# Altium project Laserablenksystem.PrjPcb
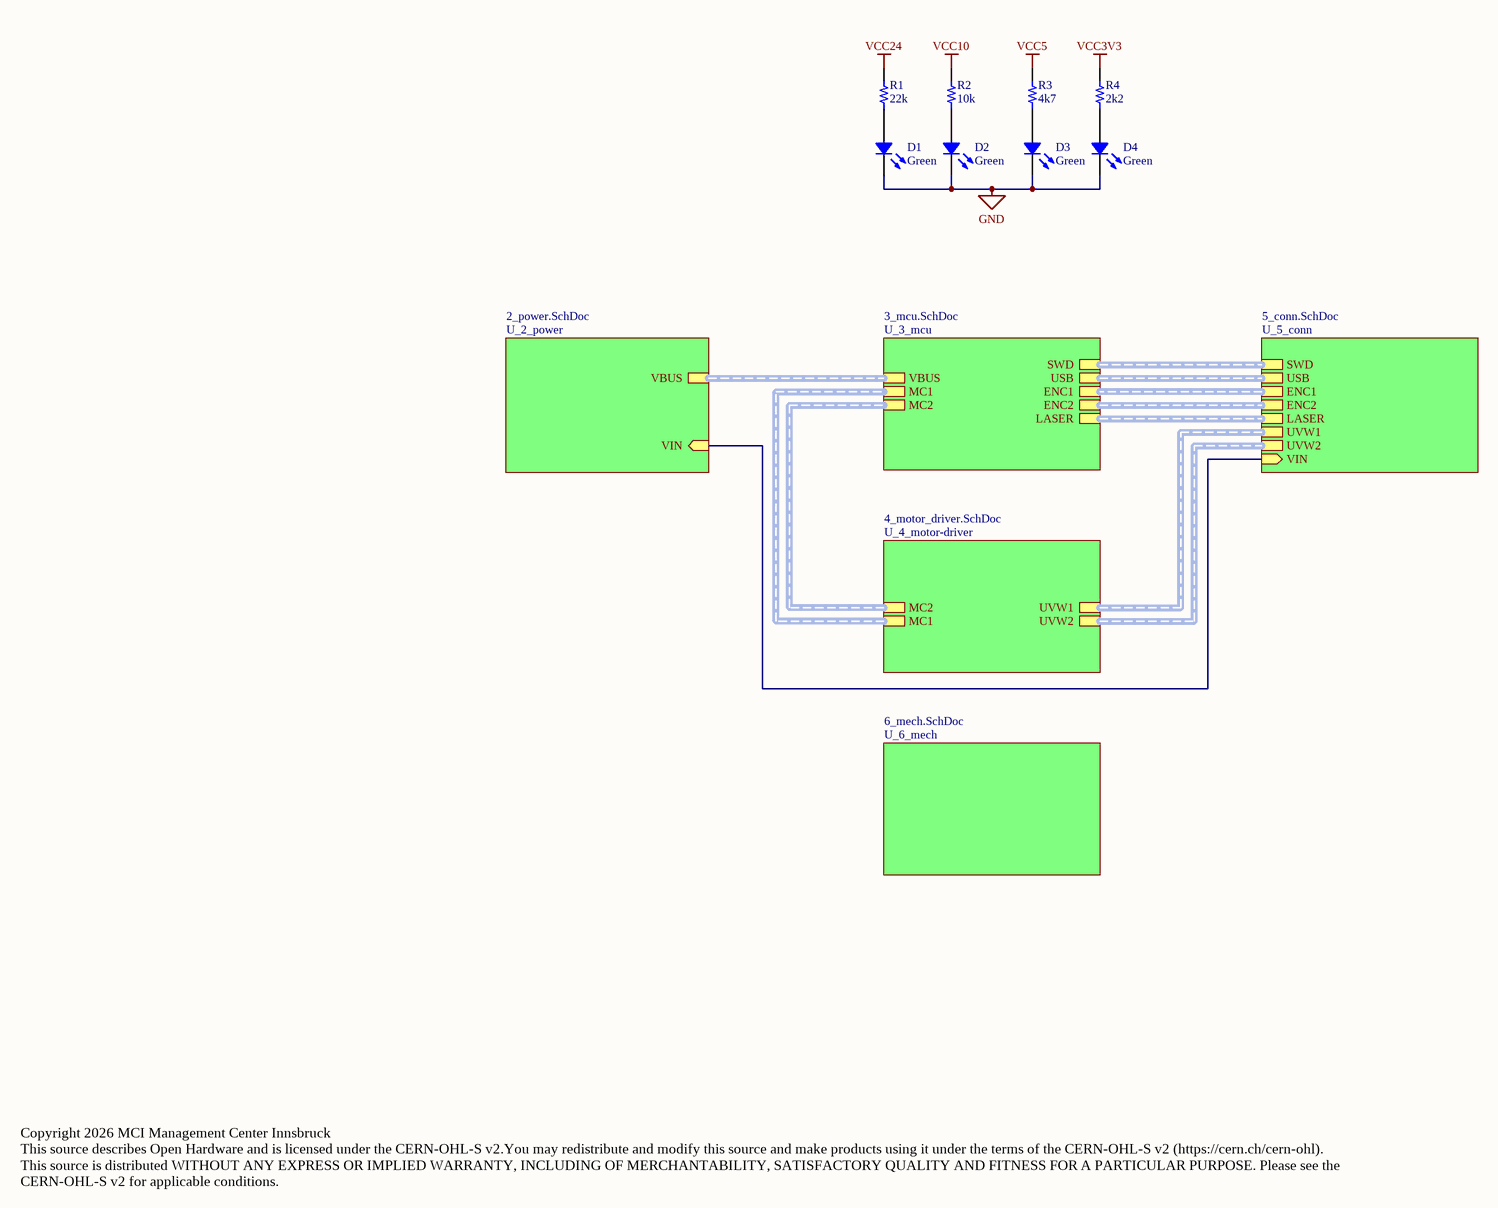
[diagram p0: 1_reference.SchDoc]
6 sheets, 152 parts. Net scope: hierarchical (ports join the sheet entries above them; power ports are global).
Board file: Laserablenksystem.PcbDoc
Sheets:
  1_reference.SchDoc
    U_2_power = 2_power.SchDoc
    U_3_mcu = 3_mcu.SchDoc
    U_5_conn = 5_conn.SchDoc
    U_4_motor-driver = 4_motor_driver.SchDoc
    U_6_mech = 6_mech.SchDoc

## Sheet 1_reference.SchDoc: Reference
size A3; CompanyName: MCI Management Center Innsbruck; Address1: Universitätsstraße 15; Address2: A-6020 Innsbruck; Revision: 1.0; SheetNumber: 1; SheetTotal: 6

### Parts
D1  Green  [LED 0805_2012 GREEN]
D2  Green  [LED 0805_2012 GREEN]
D3  Green  [LED 0805_2012 GREEN]
D4  Green  [LED 0805_2012 GREEN]
R1  22k  [RES 0603_1608]
R2  10k  [RES 0603_1608]
R3  4k7  [RES 0603_1608]
R4  2k2  [RES 0603_1608]

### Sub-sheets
U_2_power = 2_power.SchDoc: VBUS (harness Supply), VIN (in)
U_3_mcu = 3_mcu.SchDoc: MC1 (harness MC1), MC2 (harness MC2), SWD (harness SWD), USB (harness USB-C), ENC1 (harness ENC1), ENC2 (harness ENC2), LASER (harness LASER), VBUS (harness Supply)
U_4_motor-driver = 4_motor_driver.SchDoc: UVW1 (harness UVW1), UVW2 (harness UVW2), MC1 (harness MC1), MC2 (harness MC2)
U_5_conn = 5_conn.SchDoc: SWD (harness SWD), USB (harness USB-C), ENC1 (harness ENC1), ENC2 (harness ENC2), LASER (harness LASER), UVW1 (harness UVW1), UVW2 (harness UVW2), VIN (in)
U_6_mech = 6_mech.SchDoc: no entries

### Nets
GND: D1.2 D2.2 D3.2 D4.2
VCC3V3: R4.2
VCC5: R3.2
VCC10: R2.2
VCC24: R1.2
NetC2_2: sheet U_2_power/VIN, sheet U_5_conn/VIN
NetD1_1: D1.1 R1.1
NetD2_1: D2.1 R2.1
NetD3_1: D3.1 R3.1
NetD4_1: D4.1 R4.1

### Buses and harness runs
harness sheet U_2_power/VBUS = sheet U_3_mcu/VBUS
harness sheet U_3_mcu/ENC1 = sheet U_5_conn/ENC1
harness sheet U_3_mcu/ENC2 = sheet U_5_conn/ENC2
harness sheet U_3_mcu/LASER = sheet U_5_conn/LASER
harness sheet U_3_mcu/MC1 = sheet U_4_motor-driver/MC1
harness sheet U_3_mcu/MC2 = sheet U_4_motor-driver/MC2
harness sheet U_3_mcu/SWD = sheet U_5_conn/SWD
harness sheet U_3_mcu/USB = sheet U_5_conn/USB
harness sheet U_4_motor-driver/UVW1 = sheet U_5_conn/UVW1
harness sheet U_4_motor-driver/UVW2 = sheet U_5_conn/UVW2

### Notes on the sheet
- Copyright 2026 MCI Management Center Innsbruck
  This source describes Open Hardware and is licensed under the CERN-OHL-S v2.You may redistribute and modify this source and make products using it under the terms of the CERN-OHL-S v2 (https://cern.ch/cern-ohl).
  This source is distributed WITHOUT ANY EXPRESS OR IMPLIED WARRANTY, INCLUDING OF MERCHANTABILITY, SATISFACTORY QUALITY AND FITNESS FOR A PARTICULAR PURPOSE. Please see the CERN-OHL-S v2 for applicable conditions.

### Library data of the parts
D1-D4 = 5988170107F: LED GREEN CLEAR 0805 SMD; Manufacturer: Dialight; Configuration: Standard; Current - Test: 20mA; Lens Color: Colorless; Lens Size: 1.40mm x 1.25mm; Lens Style: Rectangle with Flat Top; Millicandela Rating: 20mcd; Viewing Angle: 140°; Voltage - Forward (Vf) (Typ): 2V; Wavelength - Dominant: 566nm
R1 = RC0603JR-1322KL: RES 22K OHM 5% 1/10W 0603; Manufacturer: Yageo; Power (Watts): 0.1W, 1/10W; Resistance: 22 kOhms; Temperature Coefficient: ±100ppm/°C
R2 = CRCW060310K0FKEA: RES SMD 10K OHM 1% 1/10W 0603; Manufacturer: Vishay Dale; Power (Watts): 0.1W, 1/10W; Resistance: 10 kOhms; Temperature Coefficient: ±100ppm/°C
R3 = RC0603JR-134K7L: RES 4.7K OHM 5% 1/10W 0603; Manufacturer: Yageo; Power (Watts): 0.1W, 1/10W; Resistance: 4.7 kOhms; Temperature Coefficient: ±100ppm/°C
R4 = RC0603JR-132K2L: RES 2.2K OHM 5% 1/10W 0603; Manufacturer: Yageo; Power (Watts): 0.1W, 1/10W; Resistance: 2.2 kOhms; Temperature Coefficient: ±100ppm/°C

## Sheet 2_power.SchDoc: Power Supply
size A3; CompanyName: MCI Management Center Innsbruck; Address1: Universitätsstraße 15; Address2: A-6020 Innsbruck; SheetNumber: 2; SheetTotal: 6
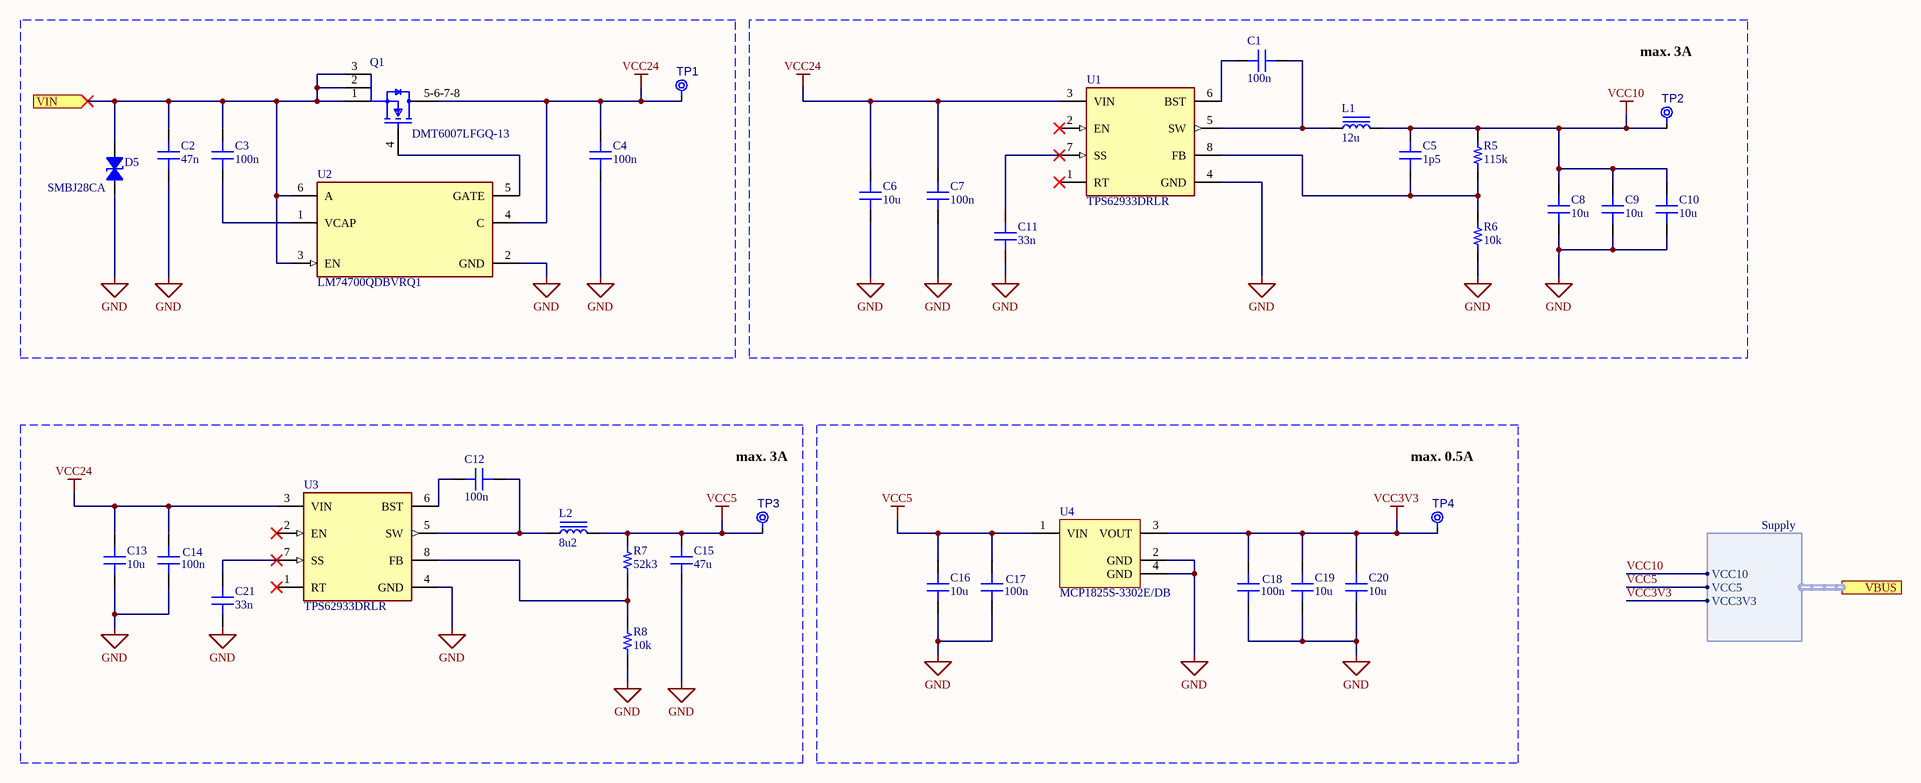
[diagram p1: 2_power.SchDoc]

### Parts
C1  Capacitance: 100n  [CAP 0805_2012]  (hidden comment: 0.1 µF)
C2  Capacitance: 47n  [CAP 0805_2012]  (hidden comment: 0.047µF)
C3  Capacitance: 100n  [CAP 0805_2012]  (hidden comment: 0.1 µF)
C4  Capacitance: 100n  [CAP 0805_2012]  (hidden comment: 0.1 µF)
C5  Capacitance: 1p5  [CAP 0603_1608]  (hidden comment: 1.5 pF)
C6  Capacitance: 10u  [CAP 1206_3216 - 0.8MM]  (hidden comment: 10 µF)
C7  Capacitance: 100n  [CAP 0805_2012]  (hidden comment: 0.1 µF)
C8  Capacitance: 10u  [CAP 1206_3216 - 0.8MM]  (hidden comment: 10 µF)
C9  Capacitance: 10u  [CAP 1206_3216 - 0.8MM]  (hidden comment: 10 µF)
C10  Capacitance: 10u  [CAP 1206_3216 - 0.8MM]  (hidden comment: 10 µF)
C11  Capacitance: 33n  [CAP 0603_1608]  (hidden comment: 0.033 µF)
C12  Capacitance: 100n  [CAP 0805_2012]  (hidden comment: 0.1 µF)
C13  Capacitance: 10u  [CAP 1206_3216 - 0.8MM]  (hidden comment: 10 µF)
C14  Capacitance: 100n  [CAP 0805_2012]  (hidden comment: 0.1 µF)
C15  47u  [CAP 1210_3225 - 1MM]
C16  Capacitance: 10u  [CAP 1206_3216 - 0.8MM]  (hidden comment: 10 µF)
C17  Capacitance: 100n  [CAP 0805_2012]  (hidden comment: 0.1 µF)
C18  Capacitance: 100n  [CAP 0805_2012]  (hidden comment: 0.1 µF)
C19  Capacitance: 10u  [CAP 1206_3216 - 0.8MM]  (hidden comment: 10 µF)
C20  Capacitance: 10u  [CAP 1206_3216 - 0.8MM]  (hidden comment: 10 µF)
C21  Capacitance: 33n  [CAP 0603_1608]  (hidden comment: 0.033 µF)
D5  SMBJ28CA  [DO214AA SMB]
L1  value 12u  [SDR1307120ML]  (hidden comment: SDR1307-120ML)
L2  value 8u2  [FP-IHLP-5050EZ-FP_3_226x4-MFG]  (hidden comment: IHLP5050EZER8R2M01)
Q1  DMT6007LFGQ-13  [FP-POWERDI3333-8-MFG]
R5  115k  [RES 0603_1608]
R6  10k  [RES 0603_1608]
R7  52k3  [RES 0603_1608]
R8  10k  [RES 0603_1608]
TP1  TPAD6R  [TP06R]  (value not drawn)  (no BOM)
TP2  TPAD6R  [TP06R]  (value not drawn)  (no BOM)
TP3  TPAD6R  [TP06R]  (value not drawn)  (no BOM)
TP4  TPAD6R  [TP06R]  (value not drawn)  (no BOM)
U1  TPS62933DRLR  [FP-DRL0008A-MFG]
U2  LM74700QDBVRQ1  [FP-DBV0006A-MFG]
U3  TPS62933DRLR  [FP-DRL0008A-MFG]
U4  MCP1825S-3302E/DB  [SOT-223-DB3_N]

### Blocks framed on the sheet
max. 3A: C1 C5-C11 L1 R5 R6 TP2 U1
max. 3A: C12-C15 C21 L2 R7 R8 TP3 U3
max. 0.5A: C16-C20 TP4 U4

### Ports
VBUS (harness Supply, see 1_reference[3B], 3_mcu[1A]), VIN (in, see 1_reference[3B], 5_conn[6A])

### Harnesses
Supply: VCC5, VCC10, VCC3V3

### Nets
GND: C2.1 C4.1 C6.1 C7.1 C8.1 C9.1 C10.1 C11.1 C13.1 C14.1 C15.1 C16.1 C17.1 C18.1 C19.1 C20.1 C21.1 D5.2 R6.1 R8.1 U1.4(GND) U2.2(GND) U3.4(GND) U4.2(GND) U4.4(GND)
VCC3V3: C18.2 C19.2 C20.2 TP4.1(TP) U4.3(VOUT) ; port VBUS.VCC3V3
VCC5: C15.2 C16.2 C17.2 L2.2 R7.2 TP3.1(TP) U4.1(VIN) ; port VBUS.VCC5
VCC10: C5.2 C8.2 C9.2 C10.2 L1.2 R5.2 TP2.1(TP) ; port VBUS.VCC10
VCC24: C4.2 C6.2 C7.2 C13.2 C14.2 Q1.5-6-7-8(D) TP1.1(TP) U1.3(VIN) U2.4(C) U3.3(VIN)
NetC1_1: C1.1 L1.1 U1.5(SW)
NetC1_2: C1.2 U1.6(BST)
NetC2_2: C2.2 C3.2 D5.1 Q1.1(S) Q1.2(S) Q1.3(S) U2.3(EN) U2.6(A) ; port VIN
NetC3_1: C3.1 U2.1(VCAP)
NetC5_1: C5.1 R5.1 R6.2 U1.8(FB)
NetC11_2: C11.2 U1.7(SS)
NetC12_1: C12.1 L2.1 U3.5(SW)
NetC12_2: C12.2 U3.6(BST)
NetC21_2: C21.2 U3.7(SS)
NetQ1_4: Q1.4(G) U2.5(GATE)
NetR7_1: R7.1 R8.2 U3.8(FB)

Not connected (* = marked no-connect by the designer): U1 1(RT)* 2(EN)*; U3 1(RT)* 2(EN)*

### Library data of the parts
C1 C3 C4 C7 C12 C14 C17 C18 = CC0805JRX7R9BB104: CAP CER 0.1UF 50V X7R 0805; manufacturer: Yageo; Tolerance: ±5%
C2 = 08055C473KAT2A: CAP CER 0.047UF 50V X7R 0805; manufacturer: AVX Corporation; Tolerance: ±10%
C5 = C0603C159C5GACTU: CAP CER 1.5PF 50V C0G/NP0 0603; manufacturer: KEMET; Temperature Coefficient: C0G, NP0; Tolerance: ±0.25pF
C6 C8-C10 C13 C16 C19 C20 = CL31A106KBHNNNE: CAP CER 10UF 50V X5R 1206; manufacturer: Samsung Electro-Mechanics; Tolerance: ±10%
C11 C21 = CC0603KRX7R9BB333: CAP CER 0.033UF 50V X7R 0603; manufacturer: Yageo; Tolerance: ±10%
C15 = GRM32ER71A476KE15L: CAP CER 47UF 10V X7R 1210; manufacturer: Murata Electronics; Capacitance: 47 µF; Tolerance: ±10%
D5 = SMBJ28CA: TVS DIODE 28VWM 45.4VC DO214AA; Manufacturer: Littelfuse Inc.; Bidirectional Channels: 1; Current - Peak Pulse (10/1000µs): 13.3A; Power Line Protection: No; Power - Peak Pulse: 600W; Type: Zener; Voltage - Breakdown (Min): 31.1V; Voltage - Clamping (Max) @ Ipp: 45.4V; Voltage - Reverse Standoff (Typ): 28V
L1 = CMP-006-00025-2: Inductor Power Unshielded Wirewound 12uH 20% 100KHz 25Q-Factor Ferrite 4.8A 0.03Ohm DCR T/R; Manufacturer_Name: Bourns; Q Factor: 25; Number of Circuits: 1; Saturation Current: 8A; Self Resonant Frequency: 20MHz; DC Resistance (DCR): 30mΩ
L2 = CMP-006-00024-1: Inductor Power Shielded Wirewound 8.2uH 20% 100KHz Powdered Iron 9.5A 0.0225Ohm DCR 5050 T/R; DC Resistance (DCR): 22.5mΩ; Core Material: Composite; Number of Circuits: 1; Saturation Current: 18A
Q1 = CMP-12801-000088-1: MOSFET BVDSS: 41V-60V POWERDI333; Drain to Source Voltage (Vdss): 60V; Continuous Drain Current (ID): 80A; Input Capacitance: 2.09nF; Rds On Max: 6mR; Max Power Dissipation: 62.5W
R5 = CRCW0603115KFKEA: RES SMD 115K OHM 1% 1/10W 0603; Manufacturer: Vishay Dale; Power (Watts): 0.1W, 1/10W; Resistance: 115 kOhms; Temperature Coefficient: ±100ppm/°C
R6 R8 = CRCW060310K0FKEA: as R2 on sheet 1_reference
R7 = RC0603FR-0752K3L: RES 52.3K OHM 1% 1/10W 0603; Manufacturer: Yageo; Power (Watts): 0.1W, 1/10W; Resistance: 52.3 kOhms; Temperature Coefficient: ±100ppm/°C
TP1-TP4 = CMP-00028-00002-3: 0.6mm round
U1 U3 = CMP-04918-000610-1: 3.8-V to 30-V, 3-A, 200-kHz to 2.2-MHz, low-IQ synchronous buck converter in SOT-583 package 8-SOT-5X3 -40 to 150
U2 = CMP-04910-000003-1: POWER MANAGEMENT; Manufacturer: Texas Instruments; Number Of Outputs: 1; Standoff Height: 0mm; Automotive Grade: Grade 1; Nominal Supply Current: 80uA; Max Junction Temp: +150°C; Max Supply Voltage: 65V; Min Supply Voltage: 3.2V
U4 = CMP-0136-00458-1: 500 mA, Low Voltage, Low Quiescent Current LDO Regulator, 3-Pin SOT-223, Extended Temperature

## Sheet 3_mcu.SchDoc: MCU
size A3; CompanyName: MCI Management Center Innsbruck; Address1: Universitätsstraße 15; Address2: A-6020 Innsbruck; SheetNumber: 3; SheetTotal: 6
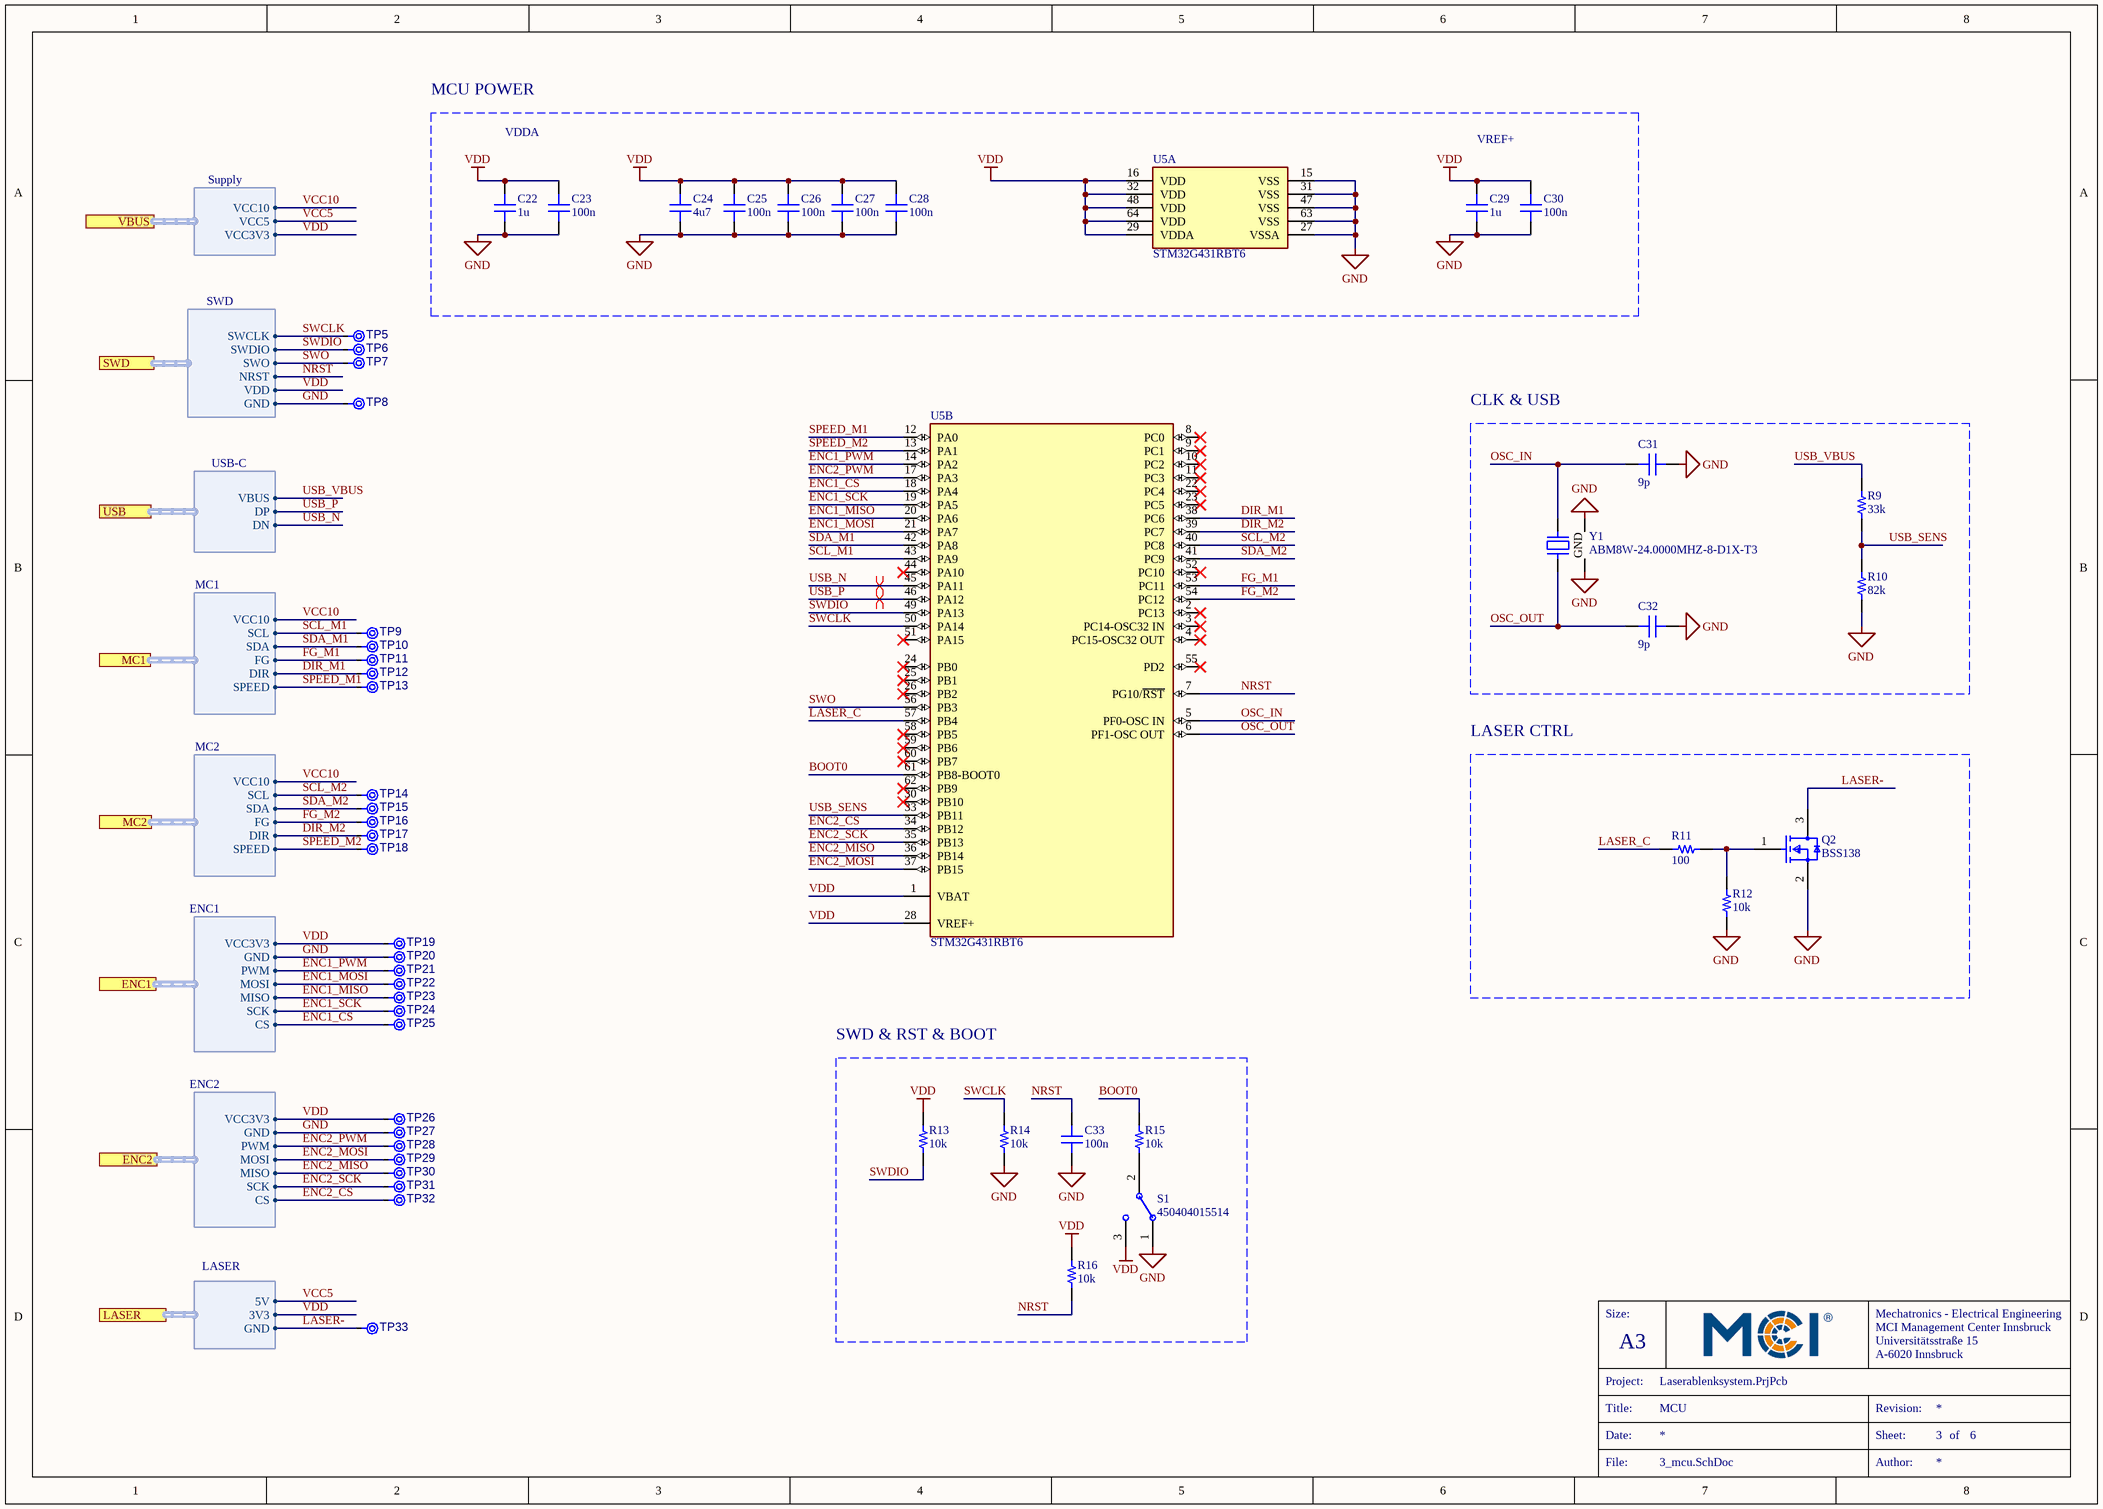
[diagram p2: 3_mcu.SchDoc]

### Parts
C22  Capacitance: 1u  [CAP 0603_1608]  (hidden comment: 1 µF)
C23  Capacitance: 100n  [CAP 0805_2012]  (hidden comment: 0.1 µF)
C24  Capacitance: 4u7  [CAP 1206_3216 - 0.8MM]  (hidden comment: 4.7 µF)
C25  Capacitance: 100n  [CAP 0805_2012]  (hidden comment: 0.1 µF)
C26  Capacitance: 100n  [CAP 0805_2012]  (hidden comment: 0.1 µF)
C27  Capacitance: 100n  [CAP 0805_2012]  (hidden comment: 0.1 µF)
C28  Capacitance: 100n  [CAP 0805_2012]  (hidden comment: 0.1 µF)
C29  Capacitance: 1u  [CAP 0603_1608]  (hidden comment: 1 µF)
C30  Capacitance: 100n  [CAP 0805_2012]  (hidden comment: 0.1 µF)
C31  Capacitance: 9p  [CAP 0402_1005]  (hidden comment: 9 pF)
C32  Capacitance: 9p  [CAP 0402_1005]  (hidden comment: 9 pF)
C33  Capacitance: 100n  [CAP 0805_2012]  (hidden comment: 0.1 µF)
Q2  BSS138  [FP-318-08-IPC_B]
R9  33k  [RES 0603_1608]
R10  82k  [RES 0603_1608]
R11  100  [RES 0603_1608]
R12  10k  [RES 0603_1608]
R13  10k  [RES 0603_1608]
R14  10k  [RES 0603_1608]
R15  10k  [RES 0603_1608]
R16  10k  [RES 0603_1608]
S1  450404015514  [WURTH WS-SLSU 450404015514]
TP5  TPAD6R  [TP06R]  (value not drawn)  (no BOM)
TP6  TPAD6R  [TP06R]  (value not drawn)  (no BOM)
TP7  TPAD6R  [TP06R]  (value not drawn)  (no BOM)
TP8  TPAD6R  [TP06R]  (value not drawn)  (no BOM)
TP9  TPAD6R  [TP06R]  (value not drawn)  (no BOM)
TP10  TPAD6R  [TP06R]  (value not drawn)  (no BOM)
TP11  TPAD6R  [TP06R]  (value not drawn)  (no BOM)
TP12  TPAD6R  [TP06R]  (value not drawn)  (no BOM)
TP13  TPAD6R  [TP06R]  (value not drawn)  (no BOM)
TP14  TPAD6R  [TP06R]  (value not drawn)  (no BOM)
TP15  TPAD6R  [TP06R]  (value not drawn)  (no BOM)
TP16  TPAD6R  [TP06R]  (value not drawn)  (no BOM)
TP17  TPAD6R  [TP06R]  (value not drawn)  (no BOM)
TP18  TPAD6R  [TP06R]  (value not drawn)  (no BOM)
TP19  TPAD6R  [TP06R]  (value not drawn)  (no BOM)
TP20  TPAD6R  [TP06R]  (value not drawn)  (no BOM)
TP21  TPAD6R  [TP06R]  (value not drawn)  (no BOM)
TP22  TPAD6R  [TP06R]  (value not drawn)  (no BOM)
TP23  TPAD6R  [TP06R]  (value not drawn)  (no BOM)
TP24  TPAD6R  [TP06R]  (value not drawn)  (no BOM)
TP25  TPAD6R  [TP06R]  (value not drawn)  (no BOM)
TP26  TPAD6R  [TP06R]  (value not drawn)  (no BOM)
TP27  TPAD6R  [TP06R]  (value not drawn)  (no BOM)
TP28  TPAD6R  [TP06R]  (value not drawn)  (no BOM)
TP29  TPAD6R  [TP06R]  (value not drawn)  (no BOM)
TP30  TPAD6R  [TP06R]  (value not drawn)  (no BOM)
TP31  TPAD6R  [TP06R]  (value not drawn)  (no BOM)
TP32  TPAD6R  [TP06R]  (value not drawn)  (no BOM)
TP33  TPAD6R  [TP06R]  (value not drawn)  (no BOM)
U5  STM32G431RBT6  [FP-LQFP64-5W-MFG]  (parts A,B of 2)
Y1  ABM8W-24.0000MHZ-8-D1X-T3  [FP-ABM8W-MFG]

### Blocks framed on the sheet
MCU POWER: C22-C30 U5
CLK & USB: C31 C32 R9 R10 Y1
LASER CTRL: Q2 R11 R12
SWD & RST & BOOT: C33 R13-R16 S1

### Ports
ENC1 (harness ENC1, see 1_reference[5B], 5_conn[1C]), ENC2 (harness ENC2, see 1_reference[5B], 5_conn[1C]), LASER (harness LASER, see 1_reference[5B], 5_conn[1D]), MC1 (harness MC1, see 1_reference[4B], 4_motor_driver[1B]), MC2 (harness MC2, see 1_reference[4B], 4_motor_driver[1B]), SWD (harness SWD, see 1_reference[5B], 5_conn[1A]), USB (harness USB-C, see 1_reference[5B], 5_conn[1B]), VBUS (harness Supply, see 1_reference[4B], 2_power[8C])

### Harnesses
SWD: SWCLK, SWDIO, GND, VDD, NRST, SWO
USB-C: DN, DP, VBUS
MC1: SPEED, DIR, FG, SDA, SCL, VCC10
MC2: SPEED, DIR, FG, SDA, SCL, VCC10
ENC1: PWM, GND, SCK, CS, VCC3V3, MOSI, MISO
ENC2: PWM, GND, SCK, CS, VCC3V3, MOSI, MISO
LASER: GND, 3V3, 5V
Supply: VCC10, VCC5, VCC3V3

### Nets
GND: C22.1 C23.1 C24.1 C25.1 C26.1 C27.1 C28.1 C29.1 C30.1 C31.1 C32.1 C33.1 Q2.2(S) R10.1 R12.1 R14.1 S1.1 TP8.1(TP) TP20.1(TP) TP27.1(TP) U5.15(VSS) U5.27(VSSA) U5.31(VSS) U5.47(VSS) U5.63(VSS) Y1.2(GND) Y1.4(GND) ; port SWD.GND, port ENC1.GND, port ENC2.GND
VCC5: port LASER.5V, port VBUS.VCC5
VCC10: port MC1.VCC10, port MC2.VCC10, port VBUS.VCC10
VDD: C22.2 C23.2 C24.2 C25.2 C26.2 C27.2 C28.2 C29.2 C30.2 R13.2 R16.2 S1.3 TP19.1(TP) TP26.1(TP) U5.1(VBAT) U5.16(VDD) U5.28(VREF+) U5.29(VDDA) U5.32(VDD) U5.48(VDD) U5.64(VDD) ; port SWD.VDD, port ENC1.VCC3V3, port ENC2.VCC3V3, port LASER.3V3, port VBUS.VCC3V3  [project net VCC3V3]
BOOT0: R15.2 U5.61(PB8-BOOT0)
DIR_M1: TP12.1(TP) U5.38(PC6) ; port MC1.DIR
DIR_M2: TP17.1(TP) U5.39(PC7) ; port MC2.DIR
ENC1_CS: TP25.1(TP) U5.18(PA4) ; port ENC1.CS
ENC1_MISO: TP23.1(TP) U5.20(PA6) ; port ENC1.MISO
ENC1_MOSI: TP22.1(TP) U5.21(PA7) ; port ENC1.MOSI
ENC1_PWM: TP21.1(TP) U5.14(PA2) ; port ENC1.PWM
ENC1_SCK: TP24.1(TP) U5.19(PA5) ; port ENC1.SCK
ENC2_CS: TP32.1(TP) U5.34(PB12) ; port ENC2.CS
ENC2_MISO: TP30.1(TP) U5.36(PB14) ; port ENC2.MISO
ENC2_MOSI: TP29.1(TP) U5.37(PB15) ; port ENC2.MOSI
ENC2_PWM: TP28.1(TP) U5.17(PA3) ; port ENC2.PWM
ENC2_SCK: TP31.1(TP) U5.35(PB13) ; port ENC2.SCK
FG_M1: TP11.1(TP) U5.53(PC11) ; port MC1.FG
FG_M2: TP16.1(TP) U5.54(PC12) ; port MC2.FG
LASER-: Q2.3(D) TP33.1(TP) ; port LASER.GND
LASER_C: R11.1 U5.57(PB4)
NRST: C33.2 R16.1 U5.7(PG10/~{RST}) ; port SWD.NRST
OSC_IN: C31.2 U5.5(PF0-OSC_IN) Y1.3
OSC_OUT: C32.2 U5.6(PF1-OSC_OUT) Y1.1
SCL_M1: TP9.1(TP) U5.43(PA9) ; port MC1.SCL
SCL_M2: TP14.1(TP) U5.40(PC8) ; port MC2.SCL
SDA_M1: TP10.1(TP) U5.42(PA8) ; port MC1.SDA
SDA_M2: TP15.1(TP) U5.41(PC9) ; port MC2.SDA
SPEED_M1: TP13.1(TP) U5.12(PA0) ; port MC1.SPEED
SPEED_M2: TP18.1(TP) U5.13(PA1) ; port MC2.SPEED
SWCLK: R14.2 TP5.1(TP) U5.50(PA14) ; port SWD.SWCLK
SWDIO: R13.1 TP6.1(TP) U5.49(PA13) ; port SWD.SWDIO
SWO: TP7.1(TP) U5.56(PB3) ; port SWD.SWO
USB_N: U5.45(PA11) ; port USB.DN
USB_P: U5.46(PA12) ; port USB.DP
USB_SENS: R9.1 R10.2 U5.33(PB11)
USB_VBUS: R9.2 ; port USB.VBUS
NetQ2_1: Q2.1(G) R11.2 R12.2
NetR15_1: R15.1 S1.2(COM)

Not connected (* = marked no-connect by the designer): U5 2(PC13)* 3(PC14-OSC32_IN)* 4(PC15-OSC32_OUT)* 8(PC0)* 9(PC1)* 10(PC2)* 11(PC3)* 22(PC4)* 23(PC5)* 24(PB0)* 25(PB1)* 26(PB2)* 30(PB10)* 44(PA10)* 51(PA15)* 52(PC10)* 55(PD2)* 58(PB5)* 59(PB6)* 60(PB7)* 62(PB9)*

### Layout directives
differential pair: USB_N, USB_P

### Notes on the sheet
- VDDA
- VREF+

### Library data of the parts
C22 C29 = EMK107B7105KA-T: CAP CER 1UF 16V X7R 0603; manufacturer: Taiyo Yuden; Tolerance: ±10%
C23 C25-C28 C30 C33 = CC0805JRX7R9BB104: as C1 on sheet 2_power
C24 = GRM31CR71H475KA12L: CAP CER 4.7UF 50V X7R 1206; manufacturer: Murata Electronics; Tolerance: ±10%
C31 C32 = CC0402CRNPO9BN9R0: CAP CER 9PF 50V C0G/NPO 0402; manufacturer: Yageo; Temperature Coefficient: C0G, NP0; Tolerance: ±0.25pF
Q2 = CMP-07173-000101-1: MOSFET N-CH 50V 220MA SOT-23; Turn-Off Delay Time: 20ns; Element Configuration: Single; Rds On Max: 3.5R; Gate to Source Voltage (Vgs): 20V; Threshold Voltage: 1.3V; Number of Elements: 1; Power Dissipation: 360mW; Rise Time: 9ns; Turn-On Delay Time: 2.5ns; Input Capacitance: 27pF; On-State Resistance: 6R
R9 = CRGCQ0603J33K: RES 33K OHM 5% 1/10W 0603; Manufacturer: TE Connectivity Passive Product; Power (Watts): 0.1W, 1/10W; Resistance: 33 kOhms; Temperature Coefficient: ±100ppm/°C
R10 = RC0603FR-1082KL: RES 82K OHM 1% 1/10W 0603; Manufacturer: Yageo; Power (Watts): 0.1W, 1/10W; Resistance: 82 kOhms; Temperature Coefficient: ±100ppm/°C
R11 = RC0603FR-07100RL: RES 100 OHM 1% 1/10W 0603; Manufacturer: Yageo; Power (Watts): 0.1W, 1/10W; Resistance: 100 Ohms; Temperature Coefficient: ±100ppm/°C
R12-R16 = CRCW060310K0FKEA: as R2 on sheet 1_reference
S1 = 450404015514: MINI SLIDE SWITCH 6.7 X 2.7 MM.; Manufacturer: Würth Elektronik; Rated Current: 300mA; Rated Voltage: 5VDC; Switching Function: On-On; Circuit: SPDT; Actuator Length: 1.50mm; Actuator Type: Standard; Contact Timing: Non-Shorting (BBM); Current Rating (Amps): 300mA (DC); Voltage Rating - DC: 5 V
TP5-TP33 = CMP-00028-00002-3: 0.6mm round
U5 = CMP-12105-000150-1: IC MCU 32BIT 128KB FLASH 64LQFP
Y1 = CMP-003-00030-1: Crystal 24MHz ±10ppm (Tol) ±20ppm (Stability) 8pF FUND 50Ohm 4-Pin SMD T/R; ESR: 25; ESR (Equivalent Series Resistance): 50Ω; Tolerance: 0.001%

## Sheet 5_conn.SchDoc: CONN
size A3; CompanyName: MCI Management Center Innsbruck; Address1: Universitätsstraße 15; Address2: A-6020 Innsbruck; SheetNumber: 5; SheetTotal: 6
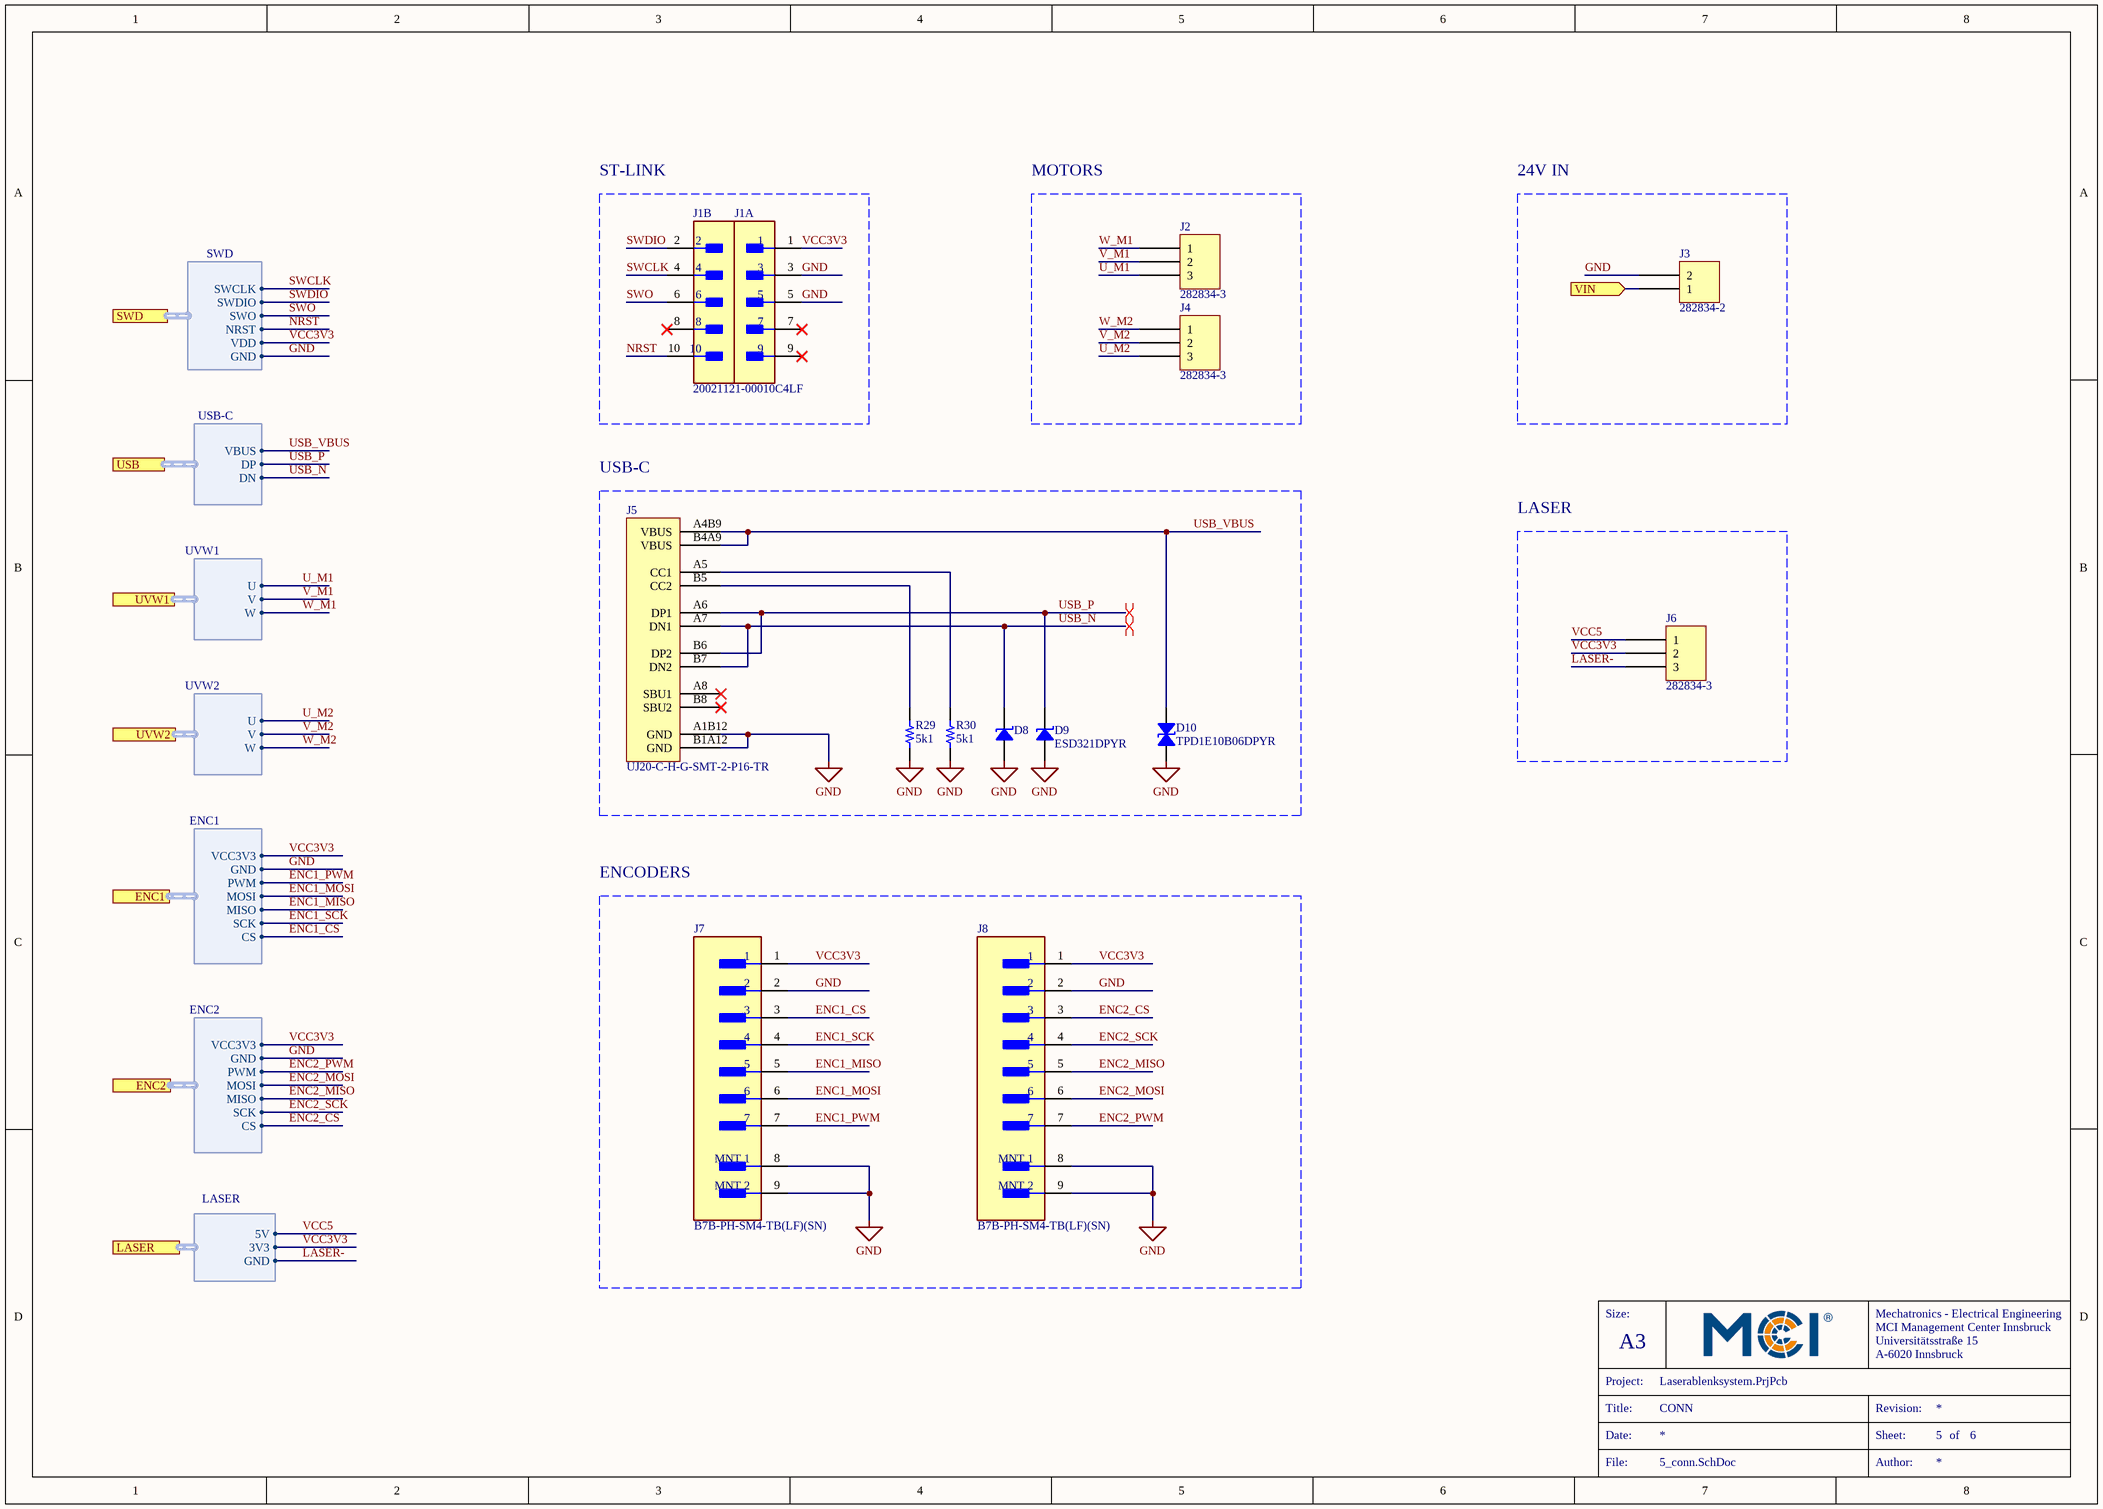
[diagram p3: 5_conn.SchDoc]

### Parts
D8  ESD321DPYR  [0402]  (value not drawn)
D9  ESD321DPYR  [0402]
D10  TPD1E10B06DPYR  [0402]
J1  20021121-00010C4LF  [FP-20021121-00010C4LF-MFG]  (value not drawn)  (parts A,B of 2)
J2  282834-3  [TE 282834-3]
J3  282834-2  [TE 282834-2]
J4  282834-3  [TE 282834-3]
J5  UJ20-C-H-G-SMT-2-P16-TR  [Same Sky UJ20-C-H-G-SMT-2-P16-TR]
J6  282834-3  [TE 282834-3]
J7  B7B-PH-SM4-TB(LF)(SN)  [FP-B7B-PH-SM4-TB_LF_SN-MFG]
J8  B7B-PH-SM4-TB(LF)(SN)  [FP-B7B-PH-SM4-TB_LF_SN-MFG]
R29  5k1  [RES 0603_1608]
R30  5k1  [RES 0603_1608]

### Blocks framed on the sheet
ST-LINK: J1
MOTORS: J2 J4
24V IN: J3
USB-C: D8-D10 J5 R29 R30
LASER: J6
ENCODERS: J7 J8

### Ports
ENC1 (harness ENC1, see 1_reference[6B], 3_mcu[1C]), ENC2 (harness ENC2, see 1_reference[6B], 3_mcu[1D]), LASER (harness LASER, see 1_reference[6B], 3_mcu[1D]), SWD (harness SWD, see 1_reference[6B], 3_mcu[1A]), USB (harness USB-C, see 1_reference[6B], 3_mcu[1B]), UVW1 (harness UVW1, see 1_reference[6B], 4_motor_driver[1C]), UVW2 (harness UVW2, see 1_reference[6B], 4_motor_driver[1C]), VIN (in, see 1_reference[6B], 2_power[1B])

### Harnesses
SWD: SWCLK, SWDIO, GND, VDD, NRST, SWO
USB-C: DN, DP, VBUS
UVW1: V, U, W
UVW2: V, U, W
ENC1: PWM, GND, SCK, CS, VCC3V3, MOSI, MISO
ENC2: PWM, GND, SCK, CS, VCC3V3, MOSI, MISO
LASER: GND, 3V3, 5V

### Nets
GND: D8.1 D9.1 D10.1 J1.3 J1.5 J3.2 J5.A1B12(GND) J5.B1A12(GND) J7.2 J7.8(MNT_1) J7.9(MNT_2) J8.2 J8.8(MNT_1) J8.9(MNT_2) R29.1 R30.1 ; port SWD.GND, port ENC1.GND, port ENC2.GND
VCC3V3: J1.1 J6.2 J7.1 J8.1 ; port SWD.VDD, port ENC1.VCC3V3, port ENC2.VCC3V3, port LASER.3V3
VCC5: J6.1 ; port LASER.5V
ENC1_CS: J7.3 ; port ENC1.CS
ENC1_MISO: J7.5 ; port ENC1.MISO
ENC1_MOSI: J7.6 ; port ENC1.MOSI
ENC1_PWM: J7.7 ; port ENC1.PWM
ENC1_SCK: J7.4 ; port ENC1.SCK
ENC2_CS: J8.3 ; port ENC2.CS
ENC2_MISO: J8.5 ; port ENC2.MISO
ENC2_MOSI: J8.6 ; port ENC2.MOSI
ENC2_PWM: J8.7 ; port ENC2.PWM
ENC2_SCK: J8.4 ; port ENC2.SCK
LASER-: J6.3 ; port LASER.GND
NRST: J1.10 ; port SWD.NRST
SWCLK: J1.4 ; port SWD.SWCLK
SWDIO: J1.2 ; port SWD.SWDIO
SWO: J1.6 ; port SWD.SWO
U_M1: J2.3 ; port UVW1.U
U_M2: J4.3 ; port UVW2.U
USB_N: D8.2 J5.A7(DN1) J5.B7(DN2) ; port USB.DN
USB_P: D9.2 J5.A6(DP1) J5.B6(DP2) ; port USB.DP
USB_VBUS: D10.2 J5.A4B9(VBUS) J5.B4A9(VBUS) ; port USB.VBUS
V_M1: J2.2 ; port UVW1.V
V_M2: J4.2 ; port UVW2.V
W_M1: J2.1 ; port UVW1.W
W_M2: J4.1 ; port UVW2.W
NetC2_2: J3.1 ; port VIN
NetJ5_A5: J5.A5(CC1) R30.2
NetJ5_B5: J5.B5(CC2) R29.2

Not connected (* = marked no-connect by the designer): J1 7* 8* 9*; J5 A8(SBU1)* B8(SBU2)*

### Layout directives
differential pair: USB_N, USB_P

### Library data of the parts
D8 D9 = ESD321DPYR: TVS DIODE 3.6VWM 6.8VC 2X1SON; Manufacturer: Texas Instruments; Capacitance @ Frequency: 0.9pF @ 1MHz; Current - Peak Pulse (10/1000µs): 6A (8/20µs); Power Line Protection: No; Power - Peak Pulse: 40W; Type: Zener; Unidirectional Channels: 1; Voltage - Breakdown (Min): 4.5V; Voltage - Clamping (Max) @ Ipp: 6.8V (Typ); Voltage - Reverse Standoff (Typ): 3.6V (Max)
D10 = TPD1E10B06DPYR: TVS DIODE 5.5VWM 14VC 2X1SON; Manufacturer: Texas Instruments; Bidirectional Channels: 1; Current - Peak Pulse (10/1000µs): 5A (8/20µs); Power Line Protection: No; Power - Peak Pulse: 90W; Type: Zener; Voltage - Breakdown (Min): 6V; Voltage - Clamping (Max) @ Ipp: 14V; Voltage - Reverse Standoff (Typ): 5.5V (Max)
J1 = CMP-15126-126517171-1: 20021121-00010C4LF Conn Unshrouded Header HDR 10 POS 1.27mm Solder ST Top Entry SMD Minitek127® T/R; Current Rating: 1A; Voltage Rating: 125V; Number of Contacts: 10; Connector Type: Header, Male Pin; Mating Post Length: 3.05mm; Insulation Resistance: 100MΩ; Gender: Male; Contact Resistance: 30mΩ; Stack Height: 3mm
J2 J4 J6 = 282834-3: TERM BLK 3P SIDE ENT 2.54MM PCB; Manufacturer: TE Connectivity AMP Connectors; Current: 10A; Mating Orientation: Horizontal with Board; Number of Levels: 1; Pitch: 0.100" (2.54mm); Positions Per Level: 3; Voltage: 150V; Wire Gauge: 16-30 AWG; Wire Termination: Screw - Rising Cage Clamp
J3 = 282834-2: TERM BLK 2P SIDE ENT 2.54MM PCB; Manufacturer: TE Connectivity AMP Connectors; Current: 10A; Mating Orientation: Horizontal with Board; Number of Levels: 1; Pitch: 0.100" (2.54mm); Positions Per Level: 2; Voltage: 150V; Wire Gauge: 16-30 AWG; Wire Termination: Screw - Rising Cage Clamp
J5 = UJ20-C-H-G-SMT-2-P16-TR: CONN RCPT USB 2.0 TYPE C SMD RA; Manufacturer: Same Sky (Formerly CUI Devices); Connector Type: USB-C (USB TYPE-C); Current Rating (Amps): 0.25A, 1.25A, 5A; Gender: Receptacle; Mating Cycles: 10000; Number of Contacts: 24 (16+8 Dummy); Number of Ports: 1; Shielding: Shielded; Specifications: USB 2.0
J7 J8 = CMP-17439-000233-1: CONN HEADER SMD 7POS 2MM; Mated Stacking Heights: 8.6mm; Number of Poles: 7; Voltage Rating (AC): 100V; Contact Resistance: 20mR; Gender: Male; Current Rating: 2A; Insulation Resistance: 1GR
R29 R30 = RMCF0603JT5K10: RES 5.1K OHM 5% 1/10W 0603; Manufacturer: Stackpole Electronics Inc; Power (Watts): 0.1W, 1/10W; Resistance: 5.1 kOhms; Temperature Coefficient: ±200ppm/°C

## Sheet 4_motor_driver.SchDoc: Motor Driver
size A3; CompanyName: MCI Management Center Innsbruck; Address1: Universitätsstraße 15; Address2: A-6020 Innsbruck; SheetNumber: 4; SheetTotal: 6
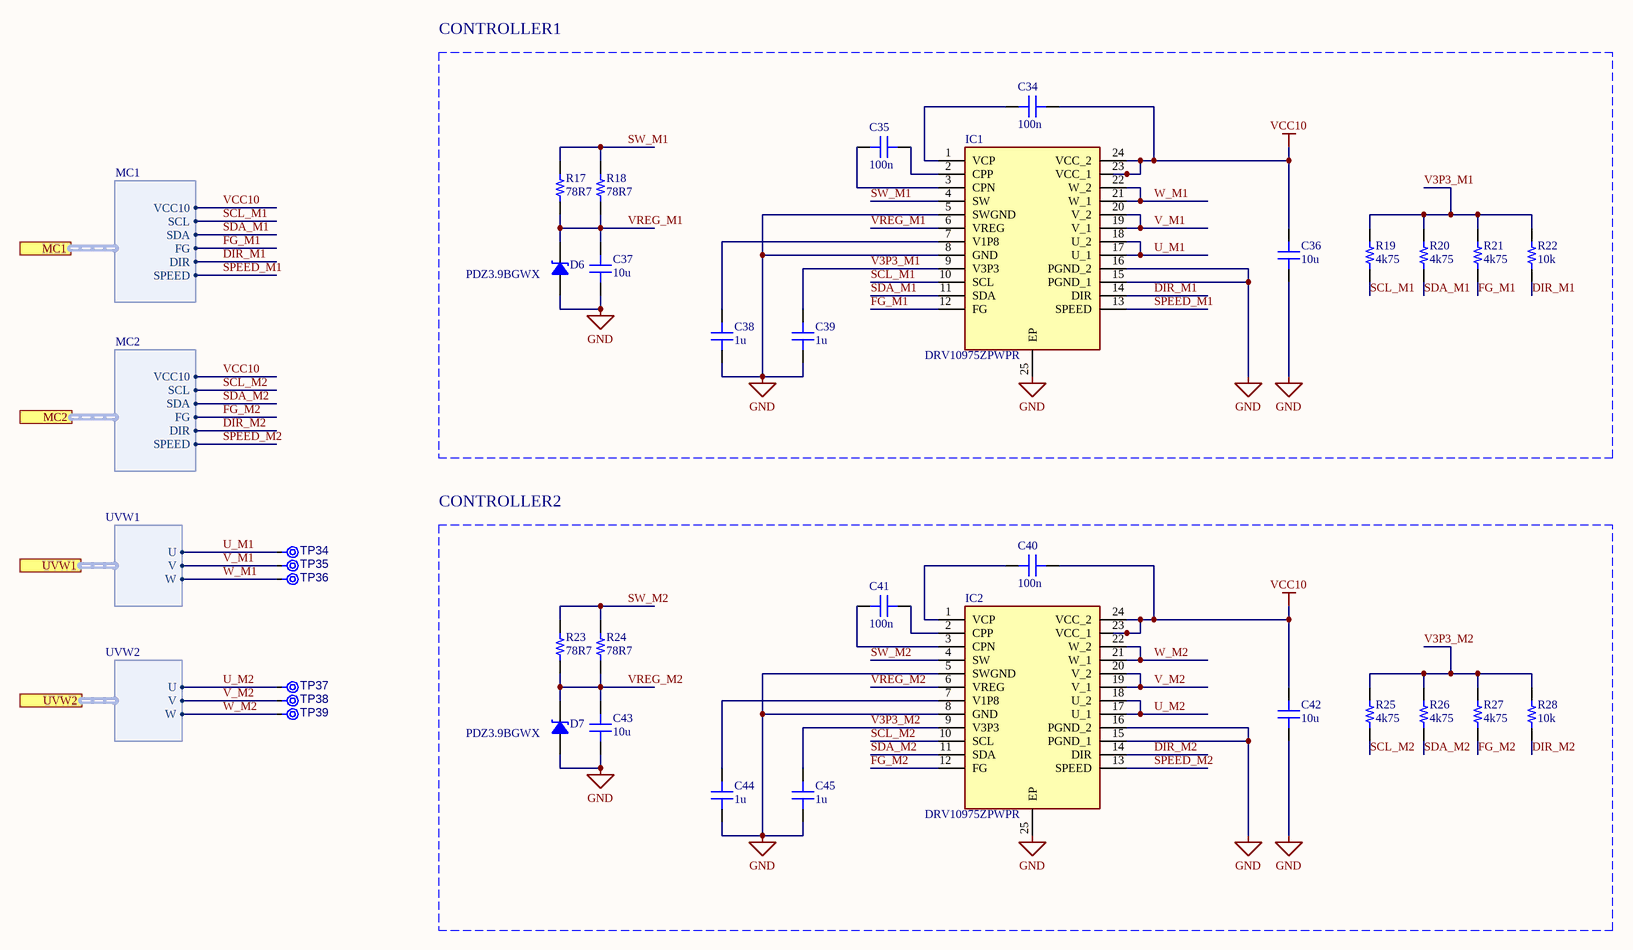
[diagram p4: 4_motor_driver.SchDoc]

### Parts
C34  Capacitance: 100n  [CAP 0805_2012]  (hidden comment: 0.1 µF)
C35  Capacitance: 100n  [CAP 0805_2012]  (hidden comment: 0.1 µF)
C36  Capacitance: 10u  [CAP 1206_3216 - 0.8MM]  (hidden comment: 10 µF)
C37  Capacitance: 10u  [CAP 1206_3216 - 0.8MM]  (hidden comment: 10 µF)
C38  Capacitance: 1u  [CAP 0402_1005]  (hidden comment: 1 µF)
C39  Capacitance: 1u  [CAP 0402_1005]  (hidden comment: 1 µF)
C40  Capacitance: 100n  [CAP 0805_2012]  (hidden comment: 0.1 µF)
C41  Capacitance: 100n  [CAP 0805_2012]  (hidden comment: 0.1 µF)
C42  Capacitance: 10u  [CAP 1206_3216 - 0.8MM]  (hidden comment: 10 µF)
C43  Capacitance: 10u  [CAP 1206_3216 - 0.8MM]  (hidden comment: 10 µF)
C44  Capacitance: 1u  [CAP 0402_1005]  (hidden comment: 1 µF)
C45  Capacitance: 1u  [CAP 0402_1005]  (hidden comment: 1 µF)
D6  PDZ3.9BGWX  [SOD-123]
D7  PDZ3.9BGWX  [SOD-123]
IC1  DRV10975ZPWPR  [SOP65P640X120-25N]
IC2  DRV10975ZPWPR  [SOP65P640X120-25N]
R17  78R7  [RES 0805_2012]
R18  78R7  [RES 0805_2012]
R19  4k75  [RES 0603_1608]
R20  4k75  [RES 0603_1608]
R21  4k75  [RES 0603_1608]
R22  10k  [RES 0603_1608]
R23  78R7  [RES 0805_2012]
R24  78R7  [RES 0805_2012]
R25  4k75  [RES 0603_1608]
R26  4k75  [RES 0603_1608]
R27  4k75  [RES 0603_1608]
R28  10k  [RES 0603_1608]
TP34  TPAD6R  [TP06R]  (value not drawn)  (no BOM)
TP35  TPAD6R  [TP06R]  (value not drawn)  (no BOM)
TP36  TPAD6R  [TP06R]  (value not drawn)  (no BOM)
TP37  TPAD6R  [TP06R]  (value not drawn)  (no BOM)
TP38  TPAD6R  [TP06R]  (value not drawn)  (no BOM)
TP39  TPAD6R  [TP06R]  (value not drawn)  (no BOM)

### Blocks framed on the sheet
CONTROLLER1: C34-C39 D6 IC1 R17-R22
CONTROLLER2: C40-C45 D7 IC2 R23-R28

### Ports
MC1 (harness MC1, see 1_reference[4C], 3_mcu[1B]), MC2 (harness MC2, see 1_reference[4C], 3_mcu[1C]), UVW1 (harness UVW1, see 1_reference[5C], 5_conn[1B]), UVW2 (harness UVW2, see 1_reference[5C], 5_conn[1B])

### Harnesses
MC1: SPEED, DIR, FG, SDA, SCL, VCC10
MC2: SPEED, DIR, FG, SDA, SCL, VCC10
UVW1: V, U, W
UVW2: V, U, W

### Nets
GND: C36.2 C37.1 C38.2 C39.2 C42.2 C43.1 C44.2 C45.2 D6.1 D7.1 IC1.5(SWGND) IC1.8(GND) IC1.15(PGND_1) IC1.16(PGND_2) IC1.25(EP) IC2.5(SWGND) IC2.8(GND) IC2.15(PGND_1) IC2.16(PGND_2) IC2.25(EP)
VCC10: C34.1 C36.1 C40.1 C42.1 IC1.23(VCC_1) IC1.24(VCC_2) IC2.23(VCC_1) IC2.24(VCC_2) ; port MC1.VCC10, port MC2.VCC10
DIR_M1: IC1.14(DIR) R22.1 ; port MC1.DIR
DIR_M2: IC2.14(DIR) R28.1 ; port MC2.DIR
FG_M1: IC1.12(FG) R21.2 ; port MC1.FG
FG_M2: IC2.12(FG) R27.2 ; port MC2.FG
SCL_M1: IC1.10(SCL) R19.2 ; port MC1.SCL
SCL_M2: IC2.10(SCL) R25.2 ; port MC2.SCL
SDA_M1: IC1.11(SDA) R20.2 ; port MC1.SDA
SDA_M2: IC2.11(SDA) R26.2 ; port MC2.SDA
SPEED_M1: IC1.13(SPEED) ; port MC1.SPEED
SPEED_M2: IC2.13(SPEED) ; port MC2.SPEED
SW_M1: IC1.4(SW) R17.1 R18.1
SW_M2: IC2.4(SW) R23.1 R24.1
U_M1: IC1.17(U_1) IC1.18(U_2) TP34.1(TP) ; port UVW1.U
U_M2: IC2.17(U_1) IC2.18(U_2) TP37.1(TP) ; port UVW2.U
V3P3_M1: C39.1 IC1.9(V3P3) R19.1 R20.1 R21.1 R22.2
V3P3_M2: C45.1 IC2.9(V3P3) R25.1 R26.1 R27.1 R28.2
V_M1: IC1.19(V_1) IC1.20(V_2) TP35.1(TP) ; port UVW1.V
V_M2: IC2.19(V_1) IC2.20(V_2) TP38.1(TP) ; port UVW2.V
VREG_M1: C37.2 D6.2 IC1.6(VREG) R17.2 R18.2
VREG_M2: C43.2 D7.2 IC2.6(VREG) R23.2 R24.2
W_M1: IC1.21(W_1) IC1.22(W_2) TP36.1(TP) ; port UVW1.W
W_M2: IC2.21(W_1) IC2.22(W_2) TP39.1(TP) ; port UVW2.W
NetC34_2: C34.2 IC1.1(VCP)
NetC35_1: C35.1 IC1.2(CPP)
NetC35_2: C35.2 IC1.3(CPN)
NetC38_1: C38.1 IC1.7(V1P8)
NetC40_2: C40.2 IC2.1(VCP)
NetC41_1: C41.1 IC2.2(CPP)
NetC41_2: C41.2 IC2.3(CPN)
NetC44_1: C44.1 IC2.7(V1P8)

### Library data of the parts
C34 C35 C40 C41 = CC0805JRX7R9BB104: as C1 on sheet 2_power
C36 C37 C42 C43 = CL31A106KBHNNNE: as C6 on sheet 2_power
C38 C39 C44 C45 = GRM155R70J105KA12J: CAP CER 1UF 6.3V X7R 0402; manufacturer: Murata Electronics; Tolerance: ±10%
D6 D7 = PDZ3.9BGWX: DIODE ZENER 3.9V 365MW SOD123W; Manufacturer: Nexperia USA Inc.; Current - Reverse Leakage @ Vr: 3 µA @ 1 V; Impedance (Max) (Zzt): 90 Ohms; Tolerance: ±2%; Voltage - Forward (Vf) (Max) @ If: 1.1 V @ 100 mA
IC1 IC2 = CMP-031-00008-1: Integrated Circuit; Manufacturer_Name: Texas Instruments
R17 R18 R23 R24 = CRCW080578R7FKEA: RES SMD 78.7 OHM 1% 1/8W 0805; Manufacturer: Vishay Dale; Power (Watts): 0.125W, 1/8W; Resistance: 78.7 Ohms; Temperature Coefficient: ±100ppm/°C
R19-R21 R25-R27 = RMCF0603FT4K75: RES 4.75K OHM 1% 1/10W 0603; Manufacturer: Stackpole Electronics Inc; Power (Watts): 0.1W, 1/10W; Resistance: 4.75 kOhms; Temperature Coefficient: ±100ppm/°C
R22 R28 = CRCW060310K0FKEA: as R2 on sheet 1_reference
TP34-TP39 = CMP-00028-00002-3: 0.6mm round

## Sheet 6_mech.SchDoc: Mechanical
size A4; CompanyName: MCI Management Center Innsbruck; Address1: Universitätsstraße 15; Address2: A-6020 Innsbruck; SheetNumber: 6; SheetTotal: 6
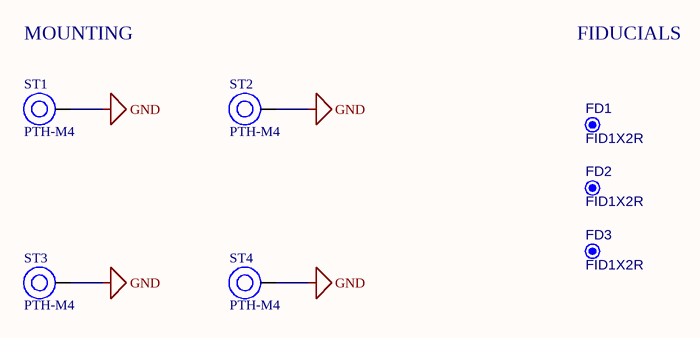
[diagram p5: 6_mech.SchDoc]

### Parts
FD1  FID1X2R  [FID1X2R]  (no BOM)
FD2  FID1X2R  [FID1X2R]  (no BOM)
FD3  FID1X2R  [FID1X2R]  (no BOM)
ST1  PTH-M4  [PTH-M4-Footprint]  (no BOM)
ST2  PTH-M4  [PTH-M4-Footprint]  (no BOM)
ST3  PTH-M4  [PTH-M4-Footprint]  (no BOM)
ST4  PTH-M4  [PTH-M4-Footprint]  (no BOM)

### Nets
GND: ST1.1(H1) ST2.1(H1) ST3.1(H1) ST4.1(H1)

Not connected (* = marked no-connect by the designer): FD1 0; FD2 0; FD3 0

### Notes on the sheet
- MOUNTING
- FIDUCIALS

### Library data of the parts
FD1-FD3 = CMP-00028-00005-4: Fiducial - Round 1x2mm
ST1-ST4 = CMP-00028-00007-3: M4 PTH (4.5mm), 7.5mm pad

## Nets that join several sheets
GND: 1_reference (D1.2 D2.2 D3.2 D4.2), 2_power (25 pins), 3_mcu (27 pins), 5_conn (16 pins), 4_motor_driver (20 pins), 6_mech (ST1.1 ST2.1 ST3.1 ST4.1)
VCC3V3: 1_reference (R4.2), 2_power (5 pins), 3_mcu (21 pins), 5_conn (J1.1 J6.2 J7.1 J8.1)
VCC5: 1_reference (R3.2), 2_power (7 pins), 5_conn (J6.1)
VCC10: 1_reference (R2.2), 2_power (7 pins), 4_motor_driver (8 pins)
VCC24: 1_reference (R1.2), 2_power (10 pins)
DIR_M1: 3_mcu (TP12.1 U5.38), 4_motor_driver (IC1.14 R22.1)
DIR_M2: 3_mcu (TP17.1 U5.39), 4_motor_driver (IC2.14 R28.1)
ENC1_CS: 3_mcu (TP25.1 U5.18), 5_conn (J7.3)
ENC1_MISO: 3_mcu (TP23.1 U5.20), 5_conn (J7.5)
ENC1_MOSI: 3_mcu (TP22.1 U5.21), 5_conn (J7.6)
ENC1_PWM: 3_mcu (TP21.1 U5.14), 5_conn (J7.7)
ENC1_SCK: 3_mcu (TP24.1 U5.19), 5_conn (J7.4)
ENC2_CS: 3_mcu (TP32.1 U5.34), 5_conn (J8.3)
ENC2_MISO: 3_mcu (TP30.1 U5.36), 5_conn (J8.5)
ENC2_MOSI: 3_mcu (TP29.1 U5.37), 5_conn (J8.6)
ENC2_PWM: 3_mcu (TP28.1 U5.17), 5_conn (J8.7)
ENC2_SCK: 3_mcu (TP31.1 U5.35), 5_conn (J8.4)
FG_M1: 3_mcu (TP11.1 U5.53), 4_motor_driver (IC1.12 R21.2)
FG_M2: 3_mcu (TP16.1 U5.54), 4_motor_driver (IC2.12 R27.2)
LASER-: 3_mcu (Q2.3 TP33.1), 5_conn (J6.3)
NetC2_2: 2_power (8 pins), 5_conn (J3.1)
NRST: 3_mcu (C33.2 R16.1 U5.7), 5_conn (J1.10)
SCL_M1: 3_mcu (TP9.1 U5.43), 4_motor_driver (IC1.10 R19.2)
SCL_M2: 3_mcu (TP14.1 U5.40), 4_motor_driver (IC2.10 R25.2)
SDA_M1: 3_mcu (TP10.1 U5.42), 4_motor_driver (IC1.11 R20.2)
SDA_M2: 3_mcu (TP15.1 U5.41), 4_motor_driver (IC2.11 R26.2)
SPEED_M1: 3_mcu (TP13.1 U5.12), 4_motor_driver (IC1.13)
SPEED_M2: 3_mcu (TP18.1 U5.13), 4_motor_driver (IC2.13)
SWCLK: 3_mcu (R14.2 TP5.1 U5.50), 5_conn (J1.4)
SWDIO: 3_mcu (R13.1 TP6.1 U5.49), 5_conn (J1.2)
SWO: 3_mcu (TP7.1 U5.56), 5_conn (J1.6)
U_M1: 5_conn (J2.3), 4_motor_driver (IC1.17 IC1.18 TP34.1)
U_M2: 5_conn (J4.3), 4_motor_driver (IC2.17 IC2.18 TP37.1)
USB_N: 3_mcu (U5.45), 5_conn (D8.2 J5.A7 J5.B7)
USB_P: 3_mcu (U5.46), 5_conn (D9.2 J5.A6 J5.B6)
USB_VBUS: 3_mcu (R9.2), 5_conn (D10.2 J5.A4B9 J5.B4A9)
V_M1: 5_conn (J2.2), 4_motor_driver (IC1.19 IC1.20 TP35.1)
V_M2: 5_conn (J4.2), 4_motor_driver (IC2.19 IC2.20 TP38.1)
W_M1: 5_conn (J2.1), 4_motor_driver (IC1.21 IC1.22 TP36.1)
W_M2: 5_conn (J4.1), 4_motor_driver (IC2.21 IC2.22 TP39.1)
